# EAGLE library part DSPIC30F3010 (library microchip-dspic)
dsPIC Motion Controller DSP
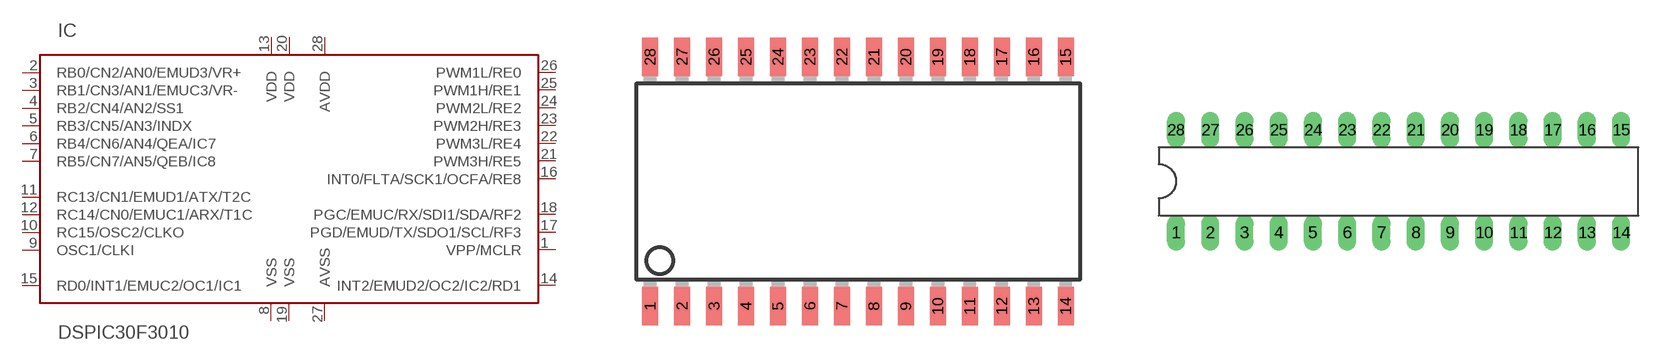
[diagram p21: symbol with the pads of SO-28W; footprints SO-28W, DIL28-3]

Designator prefix IC

## DSPIC30F3010/SO  [SO-28W]
1  VPP/MCLR  in
2  RB0/CN2/AN0/EMUD3/VR+
3  RB1/CN3/AN1/EMUC3/VR-
4  RB2/CN4/AN2/SS1
5  RB3/CN5/AN3/INDX
6  RB4/CN6/AN4/QEA/IC7
7  RB5/CN7/AN5/QEB/IC8
8  VSS  pwr
9  OSC1/CLKI  in
10  RC15/OSC2/CLKO
11  RC13/CN1/EMUD1/ATX/T2C
12  RC14/CN0/EMUC1/ARX/T1C
13  VDD  pwr
14  INT2/EMUD2/OC2/IC2/RD1
15  RD0/INT1/EMUC2/OC1/IC1
16  INT0/FLTA/SCK1/OCFA/RE8
17  PGD/EMUD/TX/SDO1/SCL/RF3
18  PGC/EMUC/RX/SDI1/SDA/RF2
19  VSS  pwr
20  VDD  pwr
21  PWM3H/RE5
22  PWM3L/RE4
23  PWM2H/RE3
24  PWM2L/RE2
25  PWM1H/RE1
26  PWM1L/RE0
27  AVSS  pwr
28  AVDD  pwr

## DSPIC30F3010/SP  [DIL28-3]
Pads as for SO-28W

## Footprint SO-28W (pad centres in mm)
Small Outline Wide Plastic Gull Wing 300-mil body, package type SO
smd 0.635 x 1.524: 1 -7.62,-4.953; 2 -6.35,-4.953; 3 -5.08,-4.953; 4 -3.81,-4.953; 5 -2.54,-4.953; 6 -1.27,-4.953; 7 0,-4.953; 8 1.27,-4.953; 9 2.54,-4.953; 10 3.81,-4.953; 11 5.08,-4.953; 12 6.35,-4.953; 13 7.62,-4.953; 14 8.89,-4.953; 15 8.89,4.953; 16 7.62,4.953; 17 6.35,4.953; 18 5.08,4.953; 19 3.81,4.953; 20 2.54,4.953; 21 1.27,4.953; 22 0,4.953; 23 -1.27,4.953; 24 -2.54,4.953; 25 -3.81,4.953; 26 -5.08,4.953; 27 -6.35,4.953; 28 -7.62,4.953

## Footprint DIL28-3 (pad centres in mm)
Dual In Line package type P
drill 0.813 long: 1 -16.51,-3.81; 2 -13.97,-3.81; 3 -11.43,-3.81; 4 -8.89,-3.81; 5 -6.35,-3.81; 6 -3.81,-3.81; 7 -1.27,-3.81; 8 1.27,-3.81; 9 3.81,-3.81; 10 6.35,-3.81; 11 8.89,-3.81; 12 11.43,-3.81; 13 13.97,-3.81; 14 16.51,-3.81; 15 16.51,3.81; 16 13.97,3.81; 17 11.43,3.81; 18 8.89,3.81; 19 6.35,3.81; 20 3.81,3.81; 21 1.27,3.81; 22 -1.27,3.81; 23 -3.81,3.81; 24 -6.35,3.81; 25 -8.89,3.81; 26 -11.43,3.81; 27 -13.97,3.81; 28 -16.51,3.81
